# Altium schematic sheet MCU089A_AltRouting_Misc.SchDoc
size 431 x 279 mm; Date: Not shown in title block; ApprovedBy: Not shown in title block; CheckedBy: Not shown in title block; Author: Not shown in title block; CompanyName: Not shown in title block; Engineer: Not shown in title block; Organization: Not shown in title block; Address1: Not shown in title block; Address2: Not shown in title block; Address3: Not shown in title block; Address4: Not shown in title block; DocumentNumber: 3; Revision: Use project parameter SCH_Rev; SheetNumber: 3; SheetTotal: 8; PageSetup: Record=PageOptions¦CenterHorizontal=True¦CenterVertical=True¦PrintScale=1.00¦XCorrection=1.00¦YCorrection=1.00¦PrintKind=0¦BorderSize=5000000¦LeftOffset=0¦BottomOffset=0¦Orientation=2¦PaperLength=1000¦PaperWidth=1000¦Scale=100¦PaperSource=15¦PrintQuality=600¦MediaType=1¦DitherType=10¦PaperKind=Letter¦PrintScaleMode=1
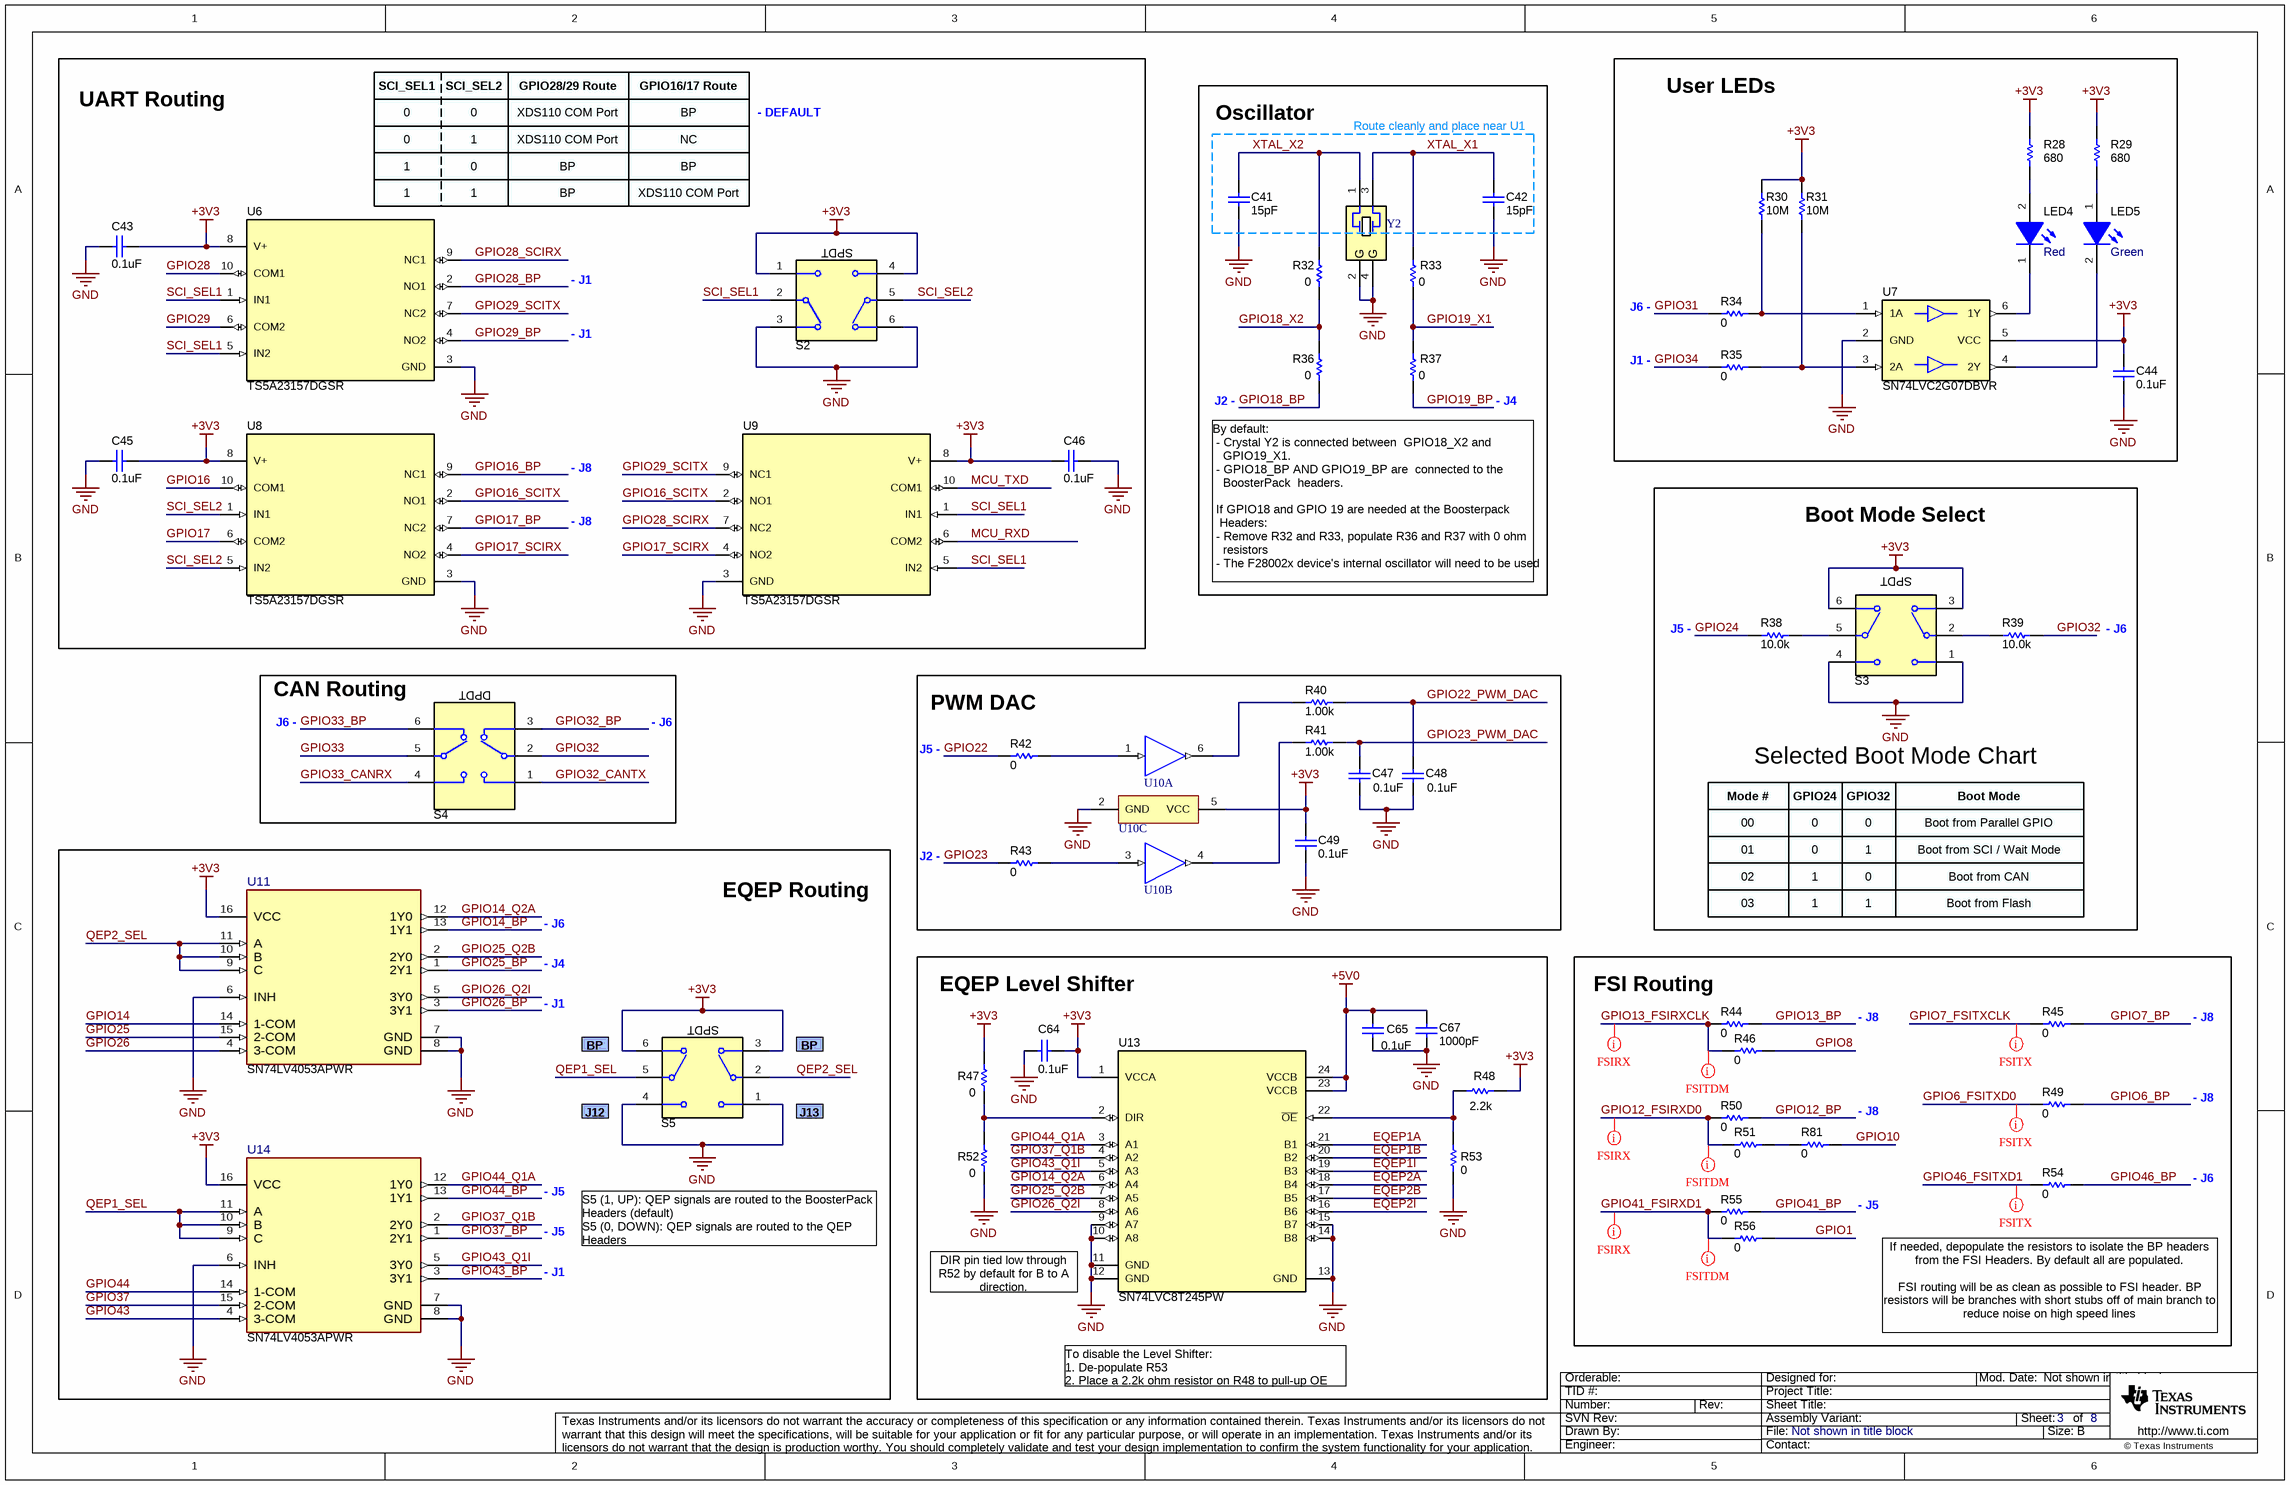
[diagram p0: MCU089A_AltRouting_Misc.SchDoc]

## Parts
C41  ValueDisplayed: 15pF  [0402]  (hidden comment: 885012005056)
C42  ValueDisplayed: 15pF  [0402]  (hidden comment: 885012005056)
C43  ValueDisplayed: 0.1uF  [0402]  (hidden comment: GRM155R71A104KA01D)
C44  ValueDisplayed: 0.1uF  [0402]  (hidden comment: GRM155R71A104KA01D)
C45  ValueDisplayed: 0.1uF  [0402]  (hidden comment: GRM155R71A104KA01D)
C46  ValueDisplayed: 0.1uF  [0402]  (hidden comment: GRM155R71A104KA01D)
C47  ValueDisplayed: 0.1uF  [0402]  (hidden comment: TMK105B7104MV-FR)
C48  ValueDisplayed: 0.1uF  [0402]  (hidden comment: TMK105B7104MV-FR)
C49  ValueDisplayed: 0.1uF  [0402]  (hidden comment: GRM155R71A104KA01D)
C64  ValueDisplayed: 0.1uF  [0402]  (hidden comment: GRM155R71A104KA01D)
C65  ValueDisplayed: 0.1uF  [0402]  (hidden comment: GRM155R71A104KA01D)
C67  ValueDisplayed: 1000pF  [0402]  (hidden comment: 885012205061)
LED4  value Red  [WL-SMCW_RED_0805]  (hidden comment: 150080SS75000)
LED5  value Green  [LED_LTST-C171]  (hidden comment: LTST-C171GKT)
R28  ValueDisplayed: 680  [0402]  (hidden comment: CRCW0402680RJNED)
R29  ValueDisplayed: 680  [0402]  (hidden comment: CRCW0402680RJNED)
R30  ValueDisplayed: 10M  [0402]  (hidden comment: CRCW040210M0JNED)
R31  ValueDisplayed: 10M  [0402]  (hidden comment: CRCW040210M0JNED)
R32  ValueDisplayed: 0  [0603]  (hidden comment: CRCW06030000Z0EA)
R33  ValueDisplayed: 0  [0603]  (hidden comment: CRCW06030000Z0EA)
R34  ValueDisplayed: 0  [0603]  (hidden comment: CRCW06030000Z0EA)
R35  ValueDisplayed: 0  [0603]  (hidden comment: CRCW06030000Z0EA)
R36  ValueDisplayed: 0  [0603]  (hidden comment: CRCW06030000Z0EA)
R37  ValueDisplayed: 0  [0603]  (hidden comment: CRCW06030000Z0EA)
R38  ValueDisplayed: 10.0k  [0603]  (hidden comment: RC0603FR-0710KL)
R39  ValueDisplayed: 10.0k  [0603]  (hidden comment: RC0603FR-0710KL)
R40  ValueDisplayed: 1.00k  [0402]  (hidden comment: CRCW04021K00FKED)
R41  ValueDisplayed: 1.00k  [0402]  (hidden comment: CRCW04021K00FKED)
R42  ValueDisplayed: 0  [0603]  (hidden comment: CRCW06030000Z0EA)
R43  ValueDisplayed: 0  [0603]  (hidden comment: CRCW06030000Z0EA)
R44  ValueDisplayed: 0  [0603]  (hidden comment: CRCW06030000Z0EA)
R45  ValueDisplayed: 0  [0603]  (hidden comment: CRCW06030000Z0EA)
R46  ValueDisplayed: 0  [0603]  (hidden comment: CRCW06030000Z0EA)
R47  ValueDisplayed: 0  [0603]  (hidden comment: CRCW06030000Z0EA)
R48  ValueDisplayed: 2.2k  [0603]  (hidden comment: CRCW06032K20JNEA)
R49  ValueDisplayed: 0  [0603]  (hidden comment: CRCW06030000Z0EA)
R50  ValueDisplayed: 0  [0603]  (hidden comment: CRCW06030000Z0EA)
R51  ValueDisplayed: 0  [0603]  (hidden comment: CRCW06030000Z0EA)
R52  ValueDisplayed: 0  [0603]  (hidden comment: CRCW06030000Z0EA)
R53  ValueDisplayed: 0  [0603]  (hidden comment: CRCW06030000Z0EA)
R54  ValueDisplayed: 0  [0603]  (hidden comment: CRCW06030000Z0EA)
R55  ValueDisplayed: 0  [0603]  (hidden comment: CRCW06030000Z0EA)
R56  ValueDisplayed: 0  [0603]  (hidden comment: CRCW06030000Z0EA)
R81  ValueDisplayed: 0  [0603]  (hidden comment: CRCW06030000Z0EA)
S2  CAS-D20TA  [SW_CAS-D20TA]  (value not drawn)
S3  CAS-D20TA  [SW_CAS-D20TA]  (value not drawn)
S4  CAS-220TA  [SW_CAS-220TA]  (value not drawn)
S5  CAS-D20TA  [SW_CAS-D20TA]  (value not drawn)
U6  TS5A23157DGSR  [DGS0010A_N]
U7  SN74LVC2G07DBVR  [DBV0006A_N]
U8  TS5A23157DGSR  [DGS0010A_N]
U9  TS5A23157DGSR  [DGS0010A_N]
U10  SN74LVC2G34DBVR  [DBV0006A_N]  (value not drawn)  (parts A,B,C of 3)
U11  SN74LV4053APWR  [PW0016A-MFG]
U13  SN74LVC8T245PW  [PW0024A_N]
U14  SN74LV4053APWR  [PW0016A-MFG]
Y2  ECS-200-18-30B-AGN-TR  [ECS_ECX-53B]  (value not drawn)

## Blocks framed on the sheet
UART Routing: C43 C45 C46 S2 U6 U8 U9
Oscillator: C41 C42 R32 R33 R36 R37 Y2
User LEDs: C44 LED4 LED5 R28-R31 R34 R35 U7
Selected Boot Mode Chart: R38 R39 S3
CAN Routing: S4
PWM DAC: C47-C49 R40-R43 U10
EQEP Routing: S5 U11 U14
EQEP Level Shifter: C64 C65 C67 R47 R48 R52 R53 U13
FSI Routing: R44-R46 R49-R51 R54-R56 R81

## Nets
+3V3: C43.1 C44.2 C45.1 C46.2 C49.2 C64.1 R28.2 R29.2 R30.2 R31.2 R47.2 R48.2 S2.1 S2.4 S3.3 S3.6 S5.3 S5.6 U6.8(V+) U7.5(VCC) U8.8(V+) U9.8(V+) U10.5(VCC) U11.16(VCC) U13.1(VCCA) U14.16(VCC)
+5V0: C65.2 C67.1 U13.23(VCCB) U13.24(VCCB)
GND: C41.2 C42.2 C43.2 C44.1 C45.2 C46.1 C47.2 C48.2 C49.1 C64.2 C65.1 C67.2 R52.1 R53.2 S2.3 S2.6 S3.1 S3.4 S5.1 S5.4 U6.3(GND) U7.2(GND) U8.3(GND) U9.3(GND) U10.2(GND) U11.6(INH) U11.7(GND) U11.8(GND) U13.9(A7) U13.10(A8) U13.11(GND) U13.12(GND) U13.13(GND) U13.14(B8) U13.15(B7) U14.6(INH) U14.7(GND) U14.8(GND) Y2.2(GND) Y2.4(GND)
EQEP1A: U13.21(B1)
EQEP1B: U13.20(B2)
EQEP1I: U13.19(B3)
EQEP2A: U13.18(B4)
EQEP2B: U13.17(B5)
EQEP2I: U13.16(B6)
GPIO1: R56.2
GPIO6_BP: R49.2
GPIO6_FSITXD0: R49.1
GPIO7_BP: R45.2
GPIO7_FSITXCLK: R45.1
GPIO8: R46.2
GPIO10: R81.2
GPIO12_BP: R50.2
GPIO12_FSIRXD0: R50.1 R51.1
GPIO13_BP: R44.2
GPIO13_FSIRXCLK: R44.1 R46.1
GPIO14: U11.14(1-COM)
GPIO14_BP: U11.13(1Y1)
GPIO14_Q2A: U11.12(1Y0) U13.6(A4)
GPIO16: U8.10(COM1)
GPIO16_BP: U8.9(NC1)
GPIO16_SCITX: U8.2(NO1) U9.2(NO1)
GPIO17: U8.6(COM2)
GPIO17_BP: U8.7(NC2)
GPIO17_SCIRX: U8.4(NO2) U9.4(NO2)
GPIO18_BP: R36.1
GPIO18_X2: R32.1 R36.2
GPIO19_BP: R37.1
GPIO19_X1: R33.1 R37.2
GPIO22: R42.1
GPIO22_PWM_DAC: C48.1 R40.2
GPIO23: R43.1
GPIO23_PWM_DAC: C47.1 R41.2
GPIO24: R38.1
GPIO25: U11.15(2-COM)
GPIO25_BP: U11.1(2Y1)
GPIO25_Q2B: U11.2(2Y0) U13.7(A5)
GPIO26: U11.4(3-COM)
GPIO26_BP: U11.3(3Y1)
GPIO26_Q2I: U11.5(3Y0) U13.8(A6)
GPIO28: U6.10(COM1)
GPIO28_BP: U6.2(NO1)
GPIO28_SCIRX: U6.9(NC1) U9.7(NC2)
GPIO29: U6.6(COM2)
GPIO29_BP: U6.4(NO2)
GPIO29_SCITX: U6.7(NC2) U9.9(NC1)
GPIO31: R34.1
GPIO32: R39.2 S4.2
GPIO32_BP: S4.3
GPIO32_CANTX: S4.1
GPIO33: S4.5
GPIO33_BP: S4.6
GPIO33_CANRX: S4.4
GPIO34: R35.1
GPIO37: U14.15(2-COM)
GPIO37_BP: U14.1(2Y1)
GPIO37_Q1B: U13.4(A2) U14.2(2Y0)
GPIO41_BP: R55.2
GPIO41_FSIRXD1: R55.1 R56.1
GPIO43: U14.4(3-COM)
GPIO43_BP: U14.3(3Y1)
GPIO43_Q1I: U13.5(A3) U14.5(3Y0)
GPIO44: U14.14(1-COM)
GPIO44_BP: U14.13(1Y1)
GPIO44_Q1A: U13.3(A1) U14.12(1Y0)
GPIO46_BP: R54.2
GPIO46_FSITXD1: R54.1
MCU_RXD: U9.6(COM2)
MCU_TXD: U9.10(COM1)
QEP1_SEL: S5.5(C) U14.9(C) U14.10(B) U14.11(A)
QEP2_SEL: S5.2(C) U11.9(C) U11.10(B) U11.11(A)
SCI_SEL1: S2.2(C) U6.1(IN1) U6.5(IN2) U9.1(IN1) U9.5(IN2)
SCI_SEL2: S2.5(C) U8.1(IN1) U8.5(IN2)
XTAL_X1: C42.1 R33.2 Y2.3
XTAL_X2: C41.1 R32.2 Y2.1
NetLED4_1: LED4.1(K) U7.6(1Y)
NetLED4_2: LED4.2(A) R28.1
NetLED5_1: LED5.1(A) R29.1
NetLED5_2: LED5.2(K) U7.4(2Y)
NetR30_1: R30.1 R34.2 U7.1(1A)
NetR31_1: R31.1 R35.2 U7.3(2A)
NetR38_2: R38.2 S3.5(C)
NetR39_1: R39.1 S3.2(C)
NetR40_1: R40.1 U10.6(1Y)
NetR41_1: R41.1 U10.4(2Y)
NetR42_2: R42.2 U10.1(1A)
NetR43_2: R43.2 U10.3(2A)
NetR47_1: R47.1 R52.2 U13.2(DIR)
NetR48_1: R48.1 R53.1 U13.22(~{OE})
NetR51_2: R51.2 R81.1

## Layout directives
net class FSIRX: GPIO12_FSIRXD0, GPIO13_FSIRXCLK, GPIO41_FSIRXD1
net class FSITX: GPIO6_FSITXD0, GPIO7_FSITXCLK, GPIO46_FSITXD1

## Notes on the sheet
- SCI_SEL1
- SCI_SEL2
- GPIO28/29 Route
- GPIO16/17 Route
- 0
- 1
- XDS110 COM Port
- BP
- NC
- - DEFAULT
- Route cleanly and place near U1
- (near U6) 1
- - J1
- (near S2) SPDT
- J6 -
- J1 -
- J2 -
- - J4
- - J8
- Boot Mode Select
- By default:
  - Crystal Y2 is connected between  GPIO18_X2 and
  GPIO19_X1.
  - GPIO18_BP AND GPIO19_BP are  connected to the
  BoosterPack  headers.
  If GPIO18 and GPIO 19 are needed at the Boosterpack
  Headers:
  - Remove R32 and R33, populate R36 and R37 with 0 ohm
  resistors
  - The F28002x device's internal oscillator will need to be used
- J5 -
- (near S3) SPDT
- - J6
- (near S4) DPDT
- Mode #
- 00
- GPIO24
- GPIO32
- Boot Mode
- Boot from Parallel GPIO
- 01
- 02
- 03
- Boot from SCI / Wait Mode
- Boot from CAN
- Boot from Flash
- (near S5) SPDT
- (near R81) - J8
- J12
- J13
- - J5
- S5 (1, UP): QEP signals are routed to the BoosterPack Headers (default)
  S5 (0, DOWN): QEP signals are routed to the QEP Headers
- (near U13) DIR pin tied low through R52 by default for B to A direction.
- If needed, depopulate the resistors to isolate the BP headers from the FSI Headers. By default all are populated.
  FSI routing will be as clean as possible to FSI header. BP resistors will be branches with short stubs off of main branch to reduce noise on high speed lines
- To disable the Level Shifter:
  1. De-populate R53
  2. Place a 2.2k ohm resistor on R48 to pull-up OE

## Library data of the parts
C41 C42 = CMP-0006216-2: CAP, CERM, 15 pF, 50 V, +/- 5%, C0G/NP0, 0402; Manufacturer: Wurth Elektronik; Polarized: N; Value: 15pF; U/M: EA; Value1: Unknown; VDC_V: 50V; TaMin_C: -55°C; TaMax_C: 125°C; SizeArea_mm2: 0.5; SizeAreaWB_mm2: 3; SizeX_mm: 1; SizeZ_mm: 0.6; AEC Category: Q200
C43-C46 C49 C64 C65 = CMP-0006629-2: CAP, CERM, 0.1 uF, 10 V, +/- 10%, X7R, 0402; Manufacturer: MuRata; Polarized: N; Value: 0.1uF; U/M: EA; Cap_F: 100nF; Value1: Unknown; VDC_V: 10V; TaMin_C: -55°C; TaMax_C: 125°C; SizeArea_mm2: 0.5; SizeAreaWB_mm2: 3; SizeX_mm: 1; SizeZ_mm: 0.6; AEC Category: Q200
C47 C48 = CMP-0006720-2: CAP, CERM, 0.1 uF, 25 V, +/- 20%, X7R, 0402; Manufacturer: Taiyo Yuden; TaMin_C: -55°C; Polarized: N; SizeAreaWB_mm2: 3; Value1: Unknown; U/M: EA; Value: 0.1uF; TaMax_C: 125°C; SizeZ_mm: 0.6; SizeX_mm: 1; SizeY_mm: 0.5; Value2: 25V; Cap_F: 100nF; AEC Category: Q200
C67 = CMP-0006231-2: CAP, CERM, 1000 pF, 50 V, +/- 10%, X7R, 0402; Manufacturer: Wurth Elektronik; Polarized: N; Value: 1000pF; U/M: EA; Cap_F: 1nF; Value1: Unknown; VDC_V: 50V; TaMin_C: -55°C; TaMax_C: 125°C; SizeArea_mm2: 0.5; SizeAreaWB_mm2: 3; SizeX_mm: 1; SizeZ_mm: 0.6; AEC Category: Q200
LED4 = CMP-0002951-3: LED, Red, SMD; Manufacturer: Wurth Elektronik; Type: AlInGaP; Vf_V: 1.9V; Io_A: 30mA; Vr_V: 5V; Ir_A: 25µA; Tjmax_C: 85°C; Power_TotalModule: 72mW; Value1: 0.072W; Angle: 140
LED5 = CMP-0002830-3: LED, Green, SMD; Manufacturer: Lite-On; Type: AlInGaP; Vf_V: 2.1V; Io_A: 20A; Value1: W; SizeAreaWB_mm2: 6.75; SizeArea_mm2: 2.5; SizeX_mm: 2; SizeY_mm: 1.25; SizeZ_mm: 1.2
R28 R29 = CMP-0026962-3: RES, 680, 5%, 0.063 W, AEC-Q200 Grade 0, 0402; Manufacturer: Vishay-Dale; Power_W: 63mW; TempCo: 200 ppm/C; Value_Code: 680R; Value: 680; EIA_Code: E24; SizeX_mm: 1; SizeY_mm: 0.5; SizeZ_mm: 0.6; Value2: 0.063W; CompType: Resistor; AEC Qualified: Y; VDC_V: 50V; AEC Category: Q200; AEC Grade: 0
R30 R31 = CMP-0026826-2: RES, 10 M, 5%, 0.063 W, AEC-Q200 Grade 0, 0402; Manufacturer: Vishay-Dale; Value: 10Meg; Value_Code: 10M0; Power_W: 63mW; Value2: 0.063W; VDC_V: 50V; TempCo: 200 ppm/C; SizeArea_mm2: 0.5; SizeX_mm: 1; SizeZ_mm: 0.6; EIA_Code: E24; AEC Category: Q200; AEC Qualified: Y; AEC Grade: 0
R32-R37 R42-R47 R49-R56 R81 = CMP-0025697-4: RES, 0, 5%, 0.1 W, AEC-Q200 Grade 0, 0603; Manufacturer: Vishay-Dale; Value: 0; Value_Code: 0000; Power_W: 100mW; Value2: 0.1W; VDC_V: 75V; TempCo: 200 ppm/C; SizeArea_mm2: 1.28; SizeX_mm: 1.6; SizeY_mm: 0.8; SizeZ_mm: 1; EIA_Code: E24; AEC Category: Q200; AEC Qualified: Y
R38 R39 = CMP-0022746-5: RES, 10.0 k, 1%, 0.1 W, 0603; Manufacturer: Yageo; Power_W: 100mW; TempCo: 100 ppm/C; Value_Code: 10k0; Value: 10.0k; EIA_Code: E96; Res_ohm: 10k; SizeX_mm: 1.6; SizeY_mm: 0.8; SizeZ_mm: 1; Value2: 0.1W; SizeArea_mm2: 1.28; AEC Qualified: N; VDC_V: 75V; AEC Category: Q200; SizeAreaWB_mm2: 4.68
R40 R41 = CMP-0026071-3: RES, 1.00 k, 1%, 0.063 W, AEC-Q200 Grade 0, 0402; Manufacturer: Vishay-Dale; Power_W: 63mW; TempCo: 100 ppm/C; Value_Code: 1k00; Value: 1.00k; EIA_Code: E96; Res_ohm: 1k; SizeX_mm: 1; SizeY_mm: 0.5; SizeZ_mm: 0.6; Value2: 0.063W; AEC Qualified: Y; VDC_V: 50V; AEC Category: Q200; AEC Grade: 0
R48 = CMP-0025769-4: RES, 2.2 k, 5%, 0.1 W, AEC-Q200 Grade 0, 0603; Manufacturer: Vishay-Dale; Value: 2.2k; Value_Code: 2k20; Power_W: 100mW; Value2: 0.1W; VDC_V: 75V; TempCo: 200 ppm/C; SizeArea_mm2: 1.28; SizeX_mm: 1.6; SizeY_mm: 0.8; SizeZ_mm: 1; EIA_Code: E24; AEC Category: Q200; AEC Qualified: Y; AEC Grade: 0
S2 S5 = CMP-0002233-1: Switch, Dual SPDT,  2 Pos, 0.1A, 6VDC, SMD; Manufacturer: Copal Electronics; VDC_V: 6V; SwitchFunction: On-On; PositionCount: 2; CurrentRating_mA: 100A
S3 = CMP-0002233-1: Switch, Dual SPDT,  2 Pos, 0.1A, 6VDC, SMD; Manufacturer: Copal Electronics; CurrentRating_mA: 100A; SwitchFunction: On-On; VDC_V: 6V; PositionCount: 2
S4 = CMP-0002123-2: SLIDE SWITCH DPDT  .1A, SMT; Manufacturer: Copal Electronics; VDC_V: 6V; SwitchFunction: On-On; PositionCount: 2; CurrentRating_mA: 100A
U6 U8 U9 = CMP-0067418-1: DUAL 10-Ohm SPDT ANALOG SWITCH, DGS0010A (VSSOP-10); Alternate PartNumber: TS5A23157DGST; Alternate Manufacturer: Texas Instruments; Green_Lifecycle: Active; SizeAreaWB_mm2: 23.6; Green_REACh: Passed; U/M: EA; SizeZ_mm: 1.1; SizeX_mm: 4.9; SizeY_mm: 3.0; SizeArea_mm2: 14.7; CompType: IC
U7 = CMP-0051789-2: Dual Buffer/Driver with Open-Drain Output, DBV0006A, LARGE T&R; Manufacturer: Texas Instruments; VCC(Min)(V): 1.65; VCC(Max)(V): 5.5; Output Type: CMOS; ICC @ Nom Voltage(Max)(mA): 0.01; Input Type: CMOS/TTL; Bits(#): 2; F @ Nom Voltage(Max)(Mhz): 150; Rating: Catalog; Technology Family: LVC; Voltage(Nom)(V): 1.8,2.5,3.3,5; Schmitt Trigger: No; Output Drive (IOL/IOH)(Max)(mA): 32/-32; tpd @ Nom Voltage(Max)(ns): 8.6,4.4,3.7,2.9; Logic: True; Sub-Family: Inverting Buffer/Driver; AEC Category: Q200; AEC Qualified: N; CompType: IC; Green_Lifecycle: Active; Green_REACh: Passed; SizeArea_mm2: 8.12; SizeAreaWB_mm2: 14.82; SizeX_mm: 2.8; SizeY_mm: 2.9; SizeZ_mm: 1.45
U10 = CMP-0051910-1: Dual Buffer Gate, DBV0006A, LARGE T&R; Manufacturer: Texas Instruments; Logic: True; F @ Nom Voltage(Max)(Mhz): 150; Output Type: CMOS; Output Drive (IOL/IOH)(Max)(mA): 32/-32; Voltage(Nom)(V): 1.8,2.5,3.3,5; 3-State Output: No; VCC(Max)(V): 5.5; ICC @ Nom Voltage(Max)(mA): 0.01; Technology Family: LVC; Input Type: CMOS/TTL; VCC(Min)(V): 1.65; Bits(#): 2; tpd @ Nom Voltage(Max)(ns): 8.6,4.4,4.1,3.2; Rating: Catalog; Sub-Family: Non-Inverting Buffer/Driver
U11 U14 = CMP-0089841-1: 3 Circuit IC Switch 2:1 75Ohm 16-TSSOP; Manufacturer: Texas Instruments; TaMax_C: +85°C; Max Supply Voltage: 5.5V; PositionCount: 3; AEC Qualified: No; SizeZ_mm: 1.2mm; Standoff Height: 0.05mm; On State Resistance: 100-225Ω; Min Supply Voltage: 2V; -3Db Bandwith: 50MHz; Nominal Supply Current: 20uA; TaMin_C: -40°C
U13 = CMP-0066458-2: 8-Bit Dual-Supply Bus Transceiver with Configurable Voltage-Level Shifting and Three-State Outputs, PW0024A (TSSOP-24); Alternate Manufacturer: Texas Instruments; SizeAreaWB_mm2: 82.32; SizeZ_mm: 1.2; SizeX_mm: 6.4; SizeY_mm: 7.8; SizeArea_mm2: 49.92; CompType: IC; AEC Category: Q200; AEC Qualified: N; Rating: Catalog
Y2 = CMP-0080365-2: Crystal, 20 MHz, 25 ppm, 18 pF, SMD; Manufacturer: ECS Inc.; Frequency Stability: 30 ppm; AEC Qualified: N; Frequency Tolerance: 25 ppm; AEC Category: Q200; TaMax_C: 85°C; Frequency_Fixed: 20MHz; TaMin_C: -40°C; Load Capacitance: 18 pF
